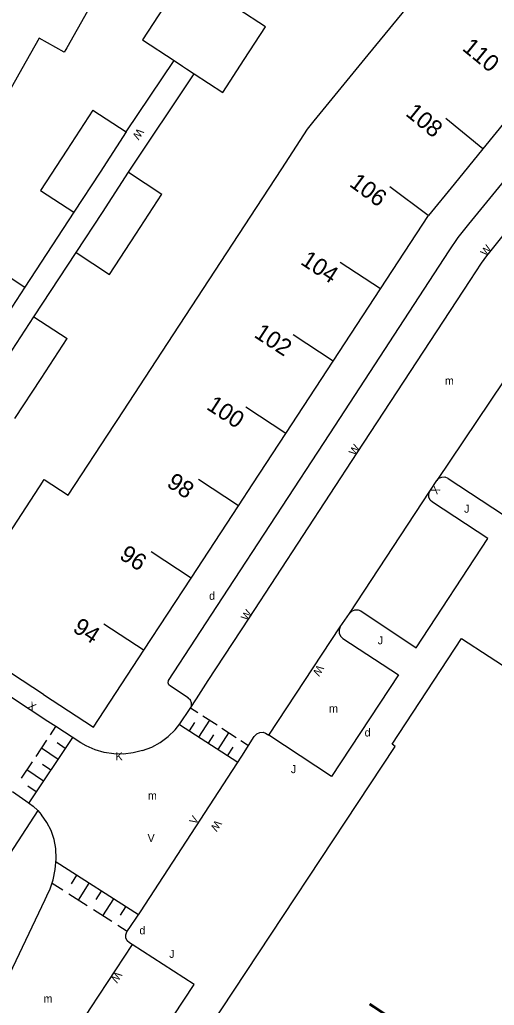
# Model space of a CAD drawing. Extents: x 134999 to 136502, y 457398 to 459002.
# Drawn here: x 135398.3 to 135427.9, y 457541.6 to 457603.2 of the extents above; entities that cross this region are included whole.
import ezdxf

# ---------------------------------------------------------------- set-up
doc = ezdxf.new("R2010")
doc.units = 0
for name, color, linetype in [('RI_DGTB_15', 7, 'Continuous'), ('RI_DGTB_2', 7, 'Continuous'), ('RI_DGTB_29', 7, 'Continuous'), ('RI_DGTB_30', 7, 'Continuous'), ('RI_DGTB_31', 7, 'Continuous'), ('RI_DGTB_35', 7, 'Continuous'), ('RI_DGTB_36', 7, 'Continuous'), ('RI_DGTB_4', 7, 'Continuous'), ('RI_DGTB_40', 7, 'Continuous'), ('RI_DGTB_43', 7, 'Continuous'), ('RI_DGTB_53', 7, 'Continuous'), ('RI_DGTB_6', 7, 'Continuous')]:
    doc.layers.add(name, color=color, linetype=linetype)

msp = doc.modelspace()

# ---------------------------------------------------------------- linework, layer by layer
at = {"layer": 'RI_DGTB_15'}
for p, q in [((135427.223, 457595.11), (135424.904, 457597.013)), ((135423.813, 457590.952), (135421.398, 457592.732)), ((135420.818, 457586.374), (135418.308, 457588.017)), ((135417.862, 457581.855), (135415.352, 457583.498)), ((135414.906, 457577.336), (135412.396, 457578.979)), ((135411.95, 457572.817), (135409.44, 457574.46)), ((135408.994, 457568.298), (135406.484, 457569.941)), ((135406.038, 457563.778), (135403.528, 457565.421))]:
    msp.add_line(p, q, dxfattribs=at)
at = {"layer": 'RI_DGTB_2'}
msp.add_line((135399.747, 457561.034), (135402.33, 457559.347), dxfattribs=at)
for points in [[(135403.799, 457606.027), (135401.21, 457601.432), (135401.148, 457601.322)], [(135420.055, 457600.988), (135422.95, 457604.523), (135423.478, 457605.165)], [(135401.148, 457601.322), (135401.053, 457601.153), (135399.485, 457602.036), (135398.387, 457600.105), (135396.92, 457597.51)], [(135416.344, 457596.455), (135416.676, 457596.862), (135420.055, 457600.988)], [(135430.64, 457599.291), (135427.223, 457595.11)], [(135414.646, 457593.871), (135416.252, 457596.342), (135416.344, 457596.455)], [(135427.223, 457595.11), (135425.432, 457592.916), (135423.82, 457590.946)], [(135413.061, 457591.447), (135414.646, 457593.871)], [(135410.105, 457586.928), (135413.061, 457591.447)], [(135420.818, 457586.374), (135423.82, 457590.946)], [(135407.15, 457582.409), (135410.105, 457586.928)], [(135417.862, 457581.855), (135420.818, 457586.374)], [(135404.396, 457578.198), (135407.15, 457582.409)], [(135414.906, 457577.336), (135417.862, 457581.855)], [(135399.724, 457574.362), (135399.731, 457574.372), (135399.791, 457574.464), (135401.3, 457573.48), (135404.194, 457577.89)], [(135404.194, 457577.89), (135404.396, 457578.198)], [(135412.842, 457574.18), (135414.906, 457577.336)], [(135396.774, 457569.839), (135399.724, 457574.362)], [(135411.949, 457572.818), (135412.842, 457574.18)], [(135408.988, 457568.301), (135411.949, 457572.818)], [(135406.028, 457563.785), (135408.988, 457568.301)], [(135399.747, 457561.034), (135395.131, 457564.049)], [(135402.33, 457559.347), (135402.884, 457558.988), (135406.028, 457563.785)]]:
    msp.add_lwpolyline(points, dxfattribs=at)
at = {"layer": 'RI_DGTB_31'}
for p, q in [((135408.95, 457560.192), (135409.409, 457559.895)), ((135409.473, 457558.363), (135410.153, 457559.411)), ((135409.707, 457559.701), (135410.6, 457559.121)), ((135400.189, 457558.512), (135400.529, 457559.02)), ((135408.254, 457559.154), (135411.895, 457556.789)), ((135408.877, 457558.749), (135409.218, 457559.274)), ((135410.898, 457558.927), (135411.792, 457558.347)), ((135398.847, 457554.263), (135401.575, 457558.336)), ((135399.282, 457557.158), (135399.962, 457558.174)), ((135410.069, 457557.975), (135410.409, 457558.5)), ((135410.664, 457557.589), (135411.345, 457558.637)), ((135412.09, 457558.153), (135412.573, 457557.84)), ((135400.661, 457556.97), (135399.622, 457557.666)), ((135401.114, 457557.647), (135400.595, 457557.994)), ((135411.26, 457557.202), (135411.6, 457557.726)), ((135398.375, 457555.804), (135399.055, 457556.819)), ((135399.754, 457555.616), (135398.715, 457556.312)), ((135400.207, 457556.293), (135399.688, 457556.641)), ((135399.3, 457554.939), (135398.781, 457555.287)), ((135405.692, 457547.253), (135400.536, 457550.544)), ((135401.815, 457549.727), (135401.479, 457549.2)), ((135400.95, 457548.796), (135400.286, 457549.22)), ((135402.583, 457549.237), (135401.91, 457548.183)), ((135402.487, 457547.815), (135401.334, 457548.551)), ((135403.351, 457548.747), (135403.015, 457548.22)), ((135404.12, 457548.256), (135403.447, 457547.203)), ((135404.887, 457547.766), (135404.551, 457547.239)), ((135404.023, 457546.835), (135402.87, 457547.571)), ((135404.984, 457546.222), (135404.407, 457546.59))]:
    msp.add_line(p, q, dxfattribs=at)
at = {"layer": 'RI_DGTB_4'}
msp.add_lwpolyline([(135408.15, 457537.56), (135409.938, 457540.239), (135410.096, 457540.15), (135421.735, 457557.785), (135421.544, 457557.912), (135425.886, 457564.512), (135429.346, 457562.279)], dxfattribs=at)
at = {"layer": 'RI_DGTB_53'}
for p, q in [((135404.925, 457596.173), (135407.912, 457600.627)), ((135405.072, 457593.654), (135409.178, 457599.8)), ((135401.649, 457591.16), (135398.581, 457586.472)), ((135399.155, 457584.625), (135401.793, 457588.634)), ((135430.55, 457583.63), (135424.35, 457574.39)), ((135423.91, 457573.73), (135424.35, 457574.39)), ((135418.89, 457566.09), (135423.91, 457573.73)), ((135418.31, 457565.25), (135418.89, 457566.09)), ((135413.834, 457558.476), (135418.31, 457565.25)), ((135408.79, 457560.809), (135407.682, 457561.539)), ((135408.279, 457559.187), (135408.922, 457560.15)), ((135405.82, 457547.45), (135412.15, 457557.18)), ((135399.388, 457553.77), (135399.615, 457553.53))]:
    msp.add_line(p, q, dxfattribs=at)
for points in [[(135407.576, 457561.896), (135410.936, 457567.059), (135417.652, 457577.313), (135425.117, 457588.734), (135425.683, 457589.574), (135426.352, 457590.404), (135434.879, 457600.826), (135437.08, 457603.55)], [(135409.321, 457560.763), (135410.053, 457561.89), (135412.617, 457565.791), (135419.364, 457576.114), (135426.43, 457586.899), (135427.13, 457587.976), (135427.473, 457588.424), (135427.58, 457588.561), (135428.585, 457589.796), (135436.452, 457599.422), (135438.811, 457602.311), (135438.157, 457603)], [(135424.35, 457574.39), (135424.478, 457574.533), (135424.654, 457574.612), (135424.846, 457574.614), (135425.023, 457574.539), (135425.06, 457574.51), (135428.51, 457572.25), (135434.06, 457580.72), (135430.67, 457582.91), (135430.532, 457583.058), (135430.461, 457583.247), (135430.468, 457583.449), (135430.55, 457583.63)], [(135418.89, 457566.09), (135419.036, 457566.233), (135419.226, 457566.311), (135419.431, 457566.31), (135419.59, 457566.25), (135423.05, 457563.94), (135427.54, 457570.76), (135424.07, 457573.03), (135423.925, 457573.168), (135423.844, 457573.352), (135423.841, 457573.552), (135423.91, 457573.73)], [(135400.029, 457559.344), (135398.919, 457560.062), (135395.401, 457562.374), (135394.533, 457562.945), (135385.74, 457569.152)], [(135418.31, 457565.25), (135418.242, 457565.071), (135418.244, 457564.865), (135418.324, 457564.675), (135418.47, 457564.53), (135421.94, 457562.25), (135417.75, 457555.91), (135413.834, 457558.476)], [(135397.809, 457554.958), (135398.646, 457554.377), (135399.114, 457554.045), (135399.388, 457553.77), (135397.391, 457550.699), (135388.301, 457556.626), (135380.824, 457562.017)], [(135407.682, 457561.539), (135407.583, 457561.626), (135407.541, 457561.763), (135407.576, 457561.896)], [(135408.921, 457560.149), (135409.003, 457560.317), (135409.008, 457560.504), (135408.936, 457560.677), (135408.798, 457560.803), (135408.789, 457560.809)], [(135408.922, 457560.15), (135409.321, 457560.763)], [(135402.089, 457558), (135400.529, 457559.02), (135400.029, 457559.344)], [(135405.949, 457557.518), (135406.516, 457557.74), (135407.049, 457558.035), (135407.539, 457558.396), (135407.977, 457558.819), (135408.278, 457559.186)], [(135412.15, 457557.18), (135412.93, 457558.399)], [(135412.93, 457558.399), (135412.95, 457558.43), (135413.091, 457558.576), (135413.277, 457558.657), (135413.481, 457558.661), (135413.63, 457558.61), (135413.834, 457558.476)], [(135405.949, 457557.518), (135405.361, 457557.37), (135404.759, 457557.301), (135404.153, 457557.311), (135403.554, 457557.401), (135402.972, 457557.569), (135402.416, 457557.812), (135402.089, 457558)], [(135400.526, 457551.403), (135400.413, 457551.972), (135400.224, 457552.52), (135399.961, 457553.036), (135399.629, 457553.512), (135399.615, 457553.53)], [(135400.073, 457548.676), (135400.138, 457548.812), (135400.352, 457549.445), (135400.488, 457550.099), (135400.546, 457550.765), (135400.526, 457551.403)], [(135394.568, 457537.057), (135395.101, 457538.216), (135395.61, 457539.32), (135399.851, 457548.209)], [(135399.851, 457548.209), (135400.073, 457548.676)], [(135405.29, 457545.397), (135405.13, 457545.5), (135404.984, 457545.634), (135404.902, 457545.814), (135404.897, 457546.011), (135404.97, 457546.195), (135405.82, 457547.45)], [(135400.851, 457538.621), (135400.971, 457538.766), (135401.139, 457538.848), (135401.327, 457538.854), (135401.5, 457538.782), (135401.551, 457538.741), (135405.001, 457536.551), (135406.54, 457538.92), (135409.17, 457542.91), (135405.29, 457545.397)], [(135405.29, 457545.397), (135402.693, 457541.457), (135400.851, 457538.621)]]:
    msp.add_lwpolyline(points, dxfattribs=at)
at = {"layer": 'RI_DGTB_6'}
for p, q in [((135402.841, 457597.535), (135404.925, 457596.173)), ((135405.072, 457593.654), (135407.157, 457592.292)), ((135399.565, 457592.522), (135401.649, 457591.16)), ((135401.793, 457588.634), (135403.878, 457587.272)), ((135396.498, 457587.836), (135398.581, 457586.472)), ((135399.155, 457584.625), (135401.238, 457583.26))]:
    msp.add_line(p, q, dxfattribs=at)
for points in [[(135407.272, 457603.97), (135405.933, 457601.922), (135407.912, 457600.627)], [(135413.634, 457602.735), (135411.898, 457603.87)], [(135412.295, 457600.687), (135413.634, 457602.735)], [(135407.912, 457600.627), (135408.444, 457600.28)], [(135409.178, 457599.8), (135410.955, 457598.638), (135412.295, 457600.687)], [(135408.444, 457600.28), (135408.695, 457600.116), (135409.178, 457599.8)], [(135402.841, 457597.535), (135401.203, 457595.028)], [(135404.925, 457596.173), (135403.287, 457593.667)], [(135401.203, 457595.028), (135399.565, 457592.522)], [(135403.287, 457593.667), (135401.649, 457591.16)], [(135403.432, 457591.144), (135405.072, 457593.654)], [(135405.518, 457589.782), (135407.157, 457592.292)], [(135401.793, 457588.634), (135403.432, 457591.144)], [(135403.878, 457587.272), (135405.518, 457589.782)], [(135398.581, 457586.472), (135396.941, 457583.967)], [(135397.516, 457582.123), (135399.155, 457584.625)], [(135399.599, 457580.758), (135401.238, 457583.26)], [(135397.96, 457578.257), (135399.599, 457580.758)]]:
    msp.add_lwpolyline(points, dxfattribs=at)

# ---------------------------------------------------------------- texts
at = {"layer": 'RI_DGTB_29'}
for p in [(135410.103, 457566.941), (135405.748, 457546.037)]:
    msp.add_text('d', height=0.5, dxfattribs=at).set_placement(p)
msp.add_text('d', height=0.5, rotation=359.99963, dxfattribs=at).set_placement((135419.83, 457558.4))
at = {"layer": 'RI_DGTB_30'}
for s, rotation, p in [('W', 235.82738, (135405.644, 457596.44)), ('W', 51.90068, (135427.426, 457588.364)), ('W', 56.83022, (135419.227, 457575.905)), ('X', 236.10527, (135424.179, 457574.128)), ('W', 56.68644, (135412.48, 457565.582)), ('W', 238.73544, (135416.891, 457562.919)), ('X', 327.10307, (135398.709, 457560.198)), ('V', 58.70684, (135409.264, 457552.859)), ('W', 237.17062, (135410.51, 457553.222)), ('W', 237.26395, (135404.275, 457543.765))]:
    msp.add_text(s, height=0.5, rotation=rotation, dxfattribs=at).set_placement(p)
for s, p in [('K', (135404.259, 457556.91)), ('V', (135406.257, 457551.813))]:
    msp.add_text(s, height=0.5, dxfattribs=at).set_placement(p)
at = {"layer": 'RI_DGTB_31'}
for p in [(135426.05, 457572.38), (135420.65, 457564.16), (135415.22, 457556.11), (135407.61, 457544.57)]:
    msp.add_text('J', height=0.5, rotation=359.99963, dxfattribs=at).set_placement(p)
at = {"layer": 'RI_DGTB_35'}
msp.add_text('94', height=1.054, rotation=326.8114, dxfattribs=at).set_placement((135401.513, 457565.003))
at = {"layer": 'RI_DGTB_36'}
for s, rotation, p in [('110', 320.6432, (135425.874, 457601.321)), ('108', 320.6432, (135422.335, 457597.241)), ('106', 323.6151, (135418.814, 457592.831)), ('104', 326.8114, (135415.762, 457587.946)), ('102', 326.8114, (135412.855, 457583.395)), ('100', 326.8114, (135409.881, 457578.888)), ('98', 326.8114, (135407.393, 457574.062)), ('96', 326.8114, (135404.431, 457569.548))]:
    msp.add_text(s, height=1.054, rotation=rotation, dxfattribs=at).set_placement(p)
at = {"layer": 'RI_DGTB_40'}
msp.add_text('s c h o o l', height=1.4, rotation=56.48467, dxfattribs=at).set_placement((135417.058, 457534.368))
at = {"layer": 'RI_DGTB_43'}
for p in [(135424.85, 457580.38), (135417.606, 457559.899), (135406.28, 457554.46)]:
    msp.add_text('m', height=0.5, rotation=359.99963, dxfattribs=at).set_placement(p)
msp.add_text('m', height=0.5, dxfattribs=at).set_placement((135399.75, 457541.775))

doc.saveas('drawing.dxf')
